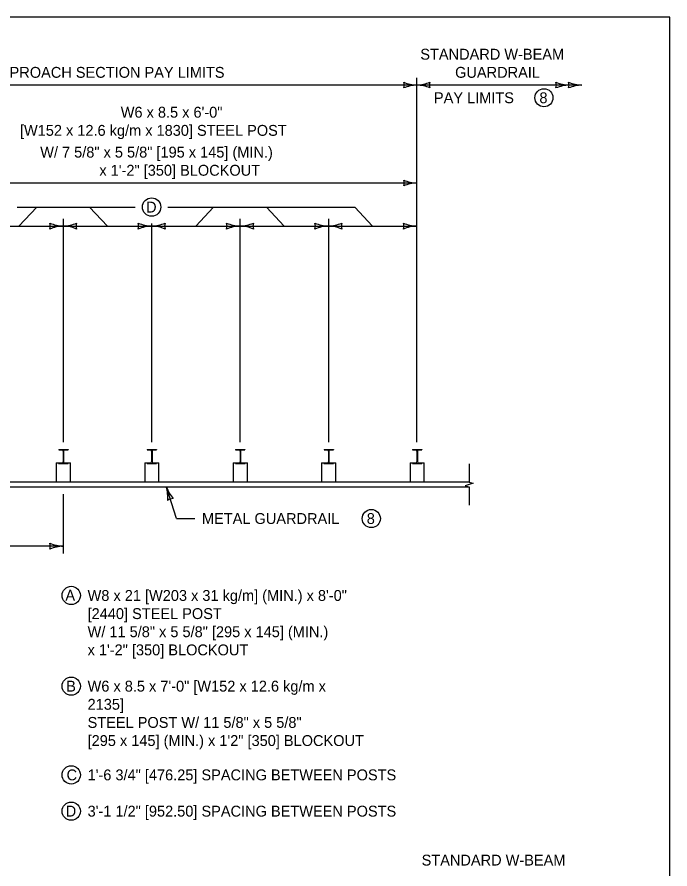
# Model space of a CAD drawing. Extents: x 49991.4 to 50021, y 49987.6 to 50011.4.
# Drawn here: x 50005.013 to 50008.615, y 50006.566 to 50011.263 of the extents above; entities that cross this region are included whole.
import ezdxf

# ---------------------------------------------------------------- set-up
doc = ezdxf.new("R2010")
doc.units = 0
for name, color, linetype in [('Level 1', 7, 'Continuous'), ('Level 2', 7, 'Continuous'), ('Level 3', 7, 'Continuous'), ('Level 6', 7, 'Continuous')]:
    doc.layers.add(name, color=color, linetype=linetype)

msp = doc.modelspace()

# ---------------------------------------------------------------- linework, layer by layer
at = {"layer": 'Level 1'}
for p, q in [((50005.2427, 50008.8793), (50005.2939, 50008.8793)), ((50005.2427, 50008.8793), (50005.2427, 50008.8765)), ((50005.2427, 50008.8765), (50005.2602, 50008.8765)), ((50005.2672, 50008.8696), (50005.2672, 50008.811)), ((50005.2694, 50008.8696), (50005.2694, 50008.811)), ((50005.2764, 50008.8765), (50005.2939, 50008.8765)), ((50005.2939, 50008.8793), (50005.2939, 50008.8765)), ((50005.7306, 50008.8793), (50005.7819, 50008.8793)), ((50005.7306, 50008.8793), (50005.7306, 50008.8765)), ((50005.7306, 50008.8765), (50005.7482, 50008.8765)), ((50005.7551, 50008.8696), (50005.7551, 50008.811)), ((50005.7573, 50008.8696), (50005.7573, 50008.811)), ((50005.7643, 50008.8765), (50005.7819, 50008.8765)), ((50005.7819, 50008.8793), (50005.7819, 50008.8765)), ((50006.2185, 50008.8793), (50006.2698, 50008.8793)), ((50006.2185, 50008.8793), (50006.2185, 50008.8765)), ((50006.2185, 50008.8765), (50006.2361, 50008.8765)), ((50006.2431, 50008.8696), (50006.2431, 50008.811)), ((50006.2453, 50008.8696), (50006.2453, 50008.811)), ((50006.2522, 50008.8765), (50006.2698, 50008.8765)), ((50006.2698, 50008.8793), (50006.2698, 50008.8765)), ((50006.7065, 50008.8793), (50006.7578, 50008.8793)), ((50006.7065, 50008.8793), (50006.7065, 50008.8765)), ((50006.7065, 50008.8765), (50006.7241, 50008.8765)), ((50006.731, 50008.8696), (50006.731, 50008.811)), ((50006.7332, 50008.8696), (50006.7332, 50008.811)), ((50006.7402, 50008.8765), (50006.7578, 50008.8765)), ((50006.7578, 50008.8793), (50006.7578, 50008.8765)), ((50007.1944, 50008.8793), (50007.2457, 50008.8793)), ((50007.1944, 50008.8793), (50007.1944, 50008.8765)), ((50007.1944, 50008.8765), (50007.212, 50008.8765)), ((50007.219, 50008.8696), (50007.219, 50008.811)), ((50007.2212, 50008.8696), (50007.2212, 50008.811)), ((50007.2281, 50008.8765), (50007.2457, 50008.8765)), ((50007.2457, 50008.8793), (50007.2457, 50008.8765)), ((50005.2293, 50008.8041), (50005.2293, 50008.7)), ((50005.2293, 50008.8041), (50005.242, 50008.8041)), ((50005.242, 50008.8013), (50005.242, 50008.8041)), ((50005.242, 50008.8013), (50005.2946, 50008.8013)), ((50005.2427, 50008.8013), (50005.2427, 50008.8041)), ((50005.2427, 50008.8041), (50005.2602, 50008.8041)), ((50005.2764, 50008.8041), (50005.2939, 50008.8041)), ((50005.2939, 50008.8013), (50005.2939, 50008.8041)), ((50005.2946, 50008.8013), (50005.2946, 50008.8041)), ((50005.2946, 50008.8041), (50005.3073, 50008.8041)), ((50005.3073, 50008.7), (50005.3073, 50008.8041)), ((50005.7172, 50008.8044), (50005.7172, 50008.7)), ((50005.7172, 50008.8041), (50005.73, 50008.8041)), ((50005.73, 50008.8013), (50005.73, 50008.8041)), ((50005.73, 50008.8013), (50005.7825, 50008.8013)), ((50005.7306, 50008.8013), (50005.7306, 50008.8041)), ((50005.7306, 50008.8041), (50005.7482, 50008.8041)), ((50005.7643, 50008.8041), (50005.7819, 50008.8041)), ((50005.7819, 50008.8013), (50005.7819, 50008.8041)), ((50005.7825, 50008.8013), (50005.7825, 50008.8041)), ((50005.7825, 50008.8041), (50005.7953, 50008.8041)), ((50005.7953, 50008.7), (50005.7953, 50008.8041)), ((50006.2051, 50008.8041), (50006.2051, 50008.7)), ((50006.2051, 50008.8041), (50006.2179, 50008.8041)), ((50006.2179, 50008.8013), (50006.2179, 50008.8041)), ((50006.2179, 50008.8013), (50006.2705, 50008.8013)), ((50006.2185, 50008.8013), (50006.2185, 50008.8041)), ((50006.2185, 50008.8041), (50006.2361, 50008.8041)), ((50006.2522, 50008.8041), (50006.2698, 50008.8041)), ((50006.2698, 50008.8013), (50006.2698, 50008.8041)), ((50006.2705, 50008.8013), (50006.2705, 50008.8041)), ((50006.2705, 50008.8041), (50006.2832, 50008.8041)), ((50006.2832, 50008.7), (50006.2832, 50008.8041)), ((50006.6931, 50008.8041), (50006.6931, 50008.7)), ((50006.6931, 50008.8041), (50006.7058, 50008.8041)), ((50006.7058, 50008.8013), (50006.7058, 50008.8041)), ((50006.7058, 50008.8013), (50006.7584, 50008.8013)), ((50006.7065, 50008.8013), (50006.7065, 50008.8041)), ((50006.7065, 50008.8041), (50006.7241, 50008.8041)), ((50006.7402, 50008.8041), (50006.7578, 50008.8041)), ((50006.7578, 50008.8013), (50006.7578, 50008.8041)), ((50006.7584, 50008.8013), (50006.7584, 50008.8041)), ((50006.7584, 50008.8041), (50006.7712, 50008.8041)), ((50006.7712, 50008.7), (50006.7712, 50008.8041)), ((50007.181, 50008.8041), (50007.181, 50008.7)), ((50007.181, 50008.8041), (50007.1938, 50008.8041)), ((50007.1938, 50008.8013), (50007.1938, 50008.8041)), ((50007.1938, 50008.8013), (50007.2464, 50008.8013)), ((50007.1944, 50008.8013), (50007.1944, 50008.8041)), ((50007.1944, 50008.8041), (50007.212, 50008.8041)), ((50007.2281, 50008.8041), (50007.2457, 50008.8041)), ((50007.2457, 50008.8013), (50007.2457, 50008.8041)), ((50007.2464, 50008.8013), (50007.2464, 50008.8041)), ((50007.2464, 50008.8041), (50007.2591, 50008.8041)), ((50007.2591, 50008.7), (50007.2591, 50008.8041)), ((50007.5069, 50008.6714), (50003.1301, 50008.6714)), ((50003.2303, 50008.7), (50007.5069, 50008.7))]:
    msp.add_line(p, q, dxfattribs=at)
msp.add_lwpolyline([(50008.6146, 50011.2628), (50000.3356, 50011.2628), (50000.3356, 50000.0624), (50008.6146, 50000.0624)], close=True, dxfattribs=at)
for centre, start, end in [((50005.2602, 50008.8696), 0, 90), ((50005.2764, 50008.8696), 90, 180), ((50005.7482, 50008.8696), 0, 90), ((50005.7643, 50008.8696), 90, 180), ((50006.2361, 50008.8696), 0, 90), ((50006.2522, 50008.8696), 90, 180), ((50006.7241, 50008.8696), 0, 90), ((50006.7402, 50008.8696), 90, 180), ((50007.212, 50008.8696), 0, 90), ((50007.2281, 50008.8696), 90, 180), ((50005.2602, 50008.811), 270, 0), ((50005.2764, 50008.811), 180, 270), ((50005.7482, 50008.811), 270, 0), ((50005.7643, 50008.811), 180, 270), ((50006.2361, 50008.811), 270, 0), ((50006.2522, 50008.811), 180, 270), ((50006.7241, 50008.811), 270, 0), ((50006.7402, 50008.811), 180, 270), ((50007.212, 50008.811), 270, 0), ((50007.2281, 50008.811), 180, 270)]:
    msp.add_arc(centre, 0.00696, start, end, dxfattribs=at)
at = {"layer": 'Level 2'}
for centre, radius in [((50007.9193, 50010.8177), 0.05), ((50005.7549, 50010.215), 0.0505), ((50006.9668, 50008.4978), 0.05), ((50005.3115, 50008.0736), 0.0504), ((50005.3115, 50007.5736), 0.0504), ((50005.3115, 50007.0844), 0.0504), ((50005.3115, 50006.8844), 0.0505)]:
    msp.add_circle(centre, radius, dxfattribs=at)
at = {"layer": 'Level 3'}
for p, q in [((50007.2181, 50008.9193), (50007.2181, 50010.9278)), ((50007.2181, 50010.8878), (50003.3165, 50010.8878)), ((50008.1278, 50010.8878), (50007.2181, 50010.8878)), ((50004.7796, 50010.3479), (50007.2181, 50010.3479)), ((50005.0126, 50010.215), (50005.6645, 50010.215)), ((50005.1215, 50010.215), (50005.0234, 50010.1105)), ((50005.4129, 50010.215), (50005.5111, 50010.1105)), ((50005.8454, 50010.215), (50006.8761, 50010.215)), ((50006.0969, 50010.215), (50005.9988, 50010.1105)), ((50006.3883, 50010.215), (50006.4865, 50010.1105)), ((50006.8761, 50010.215), (50006.9742, 50010.1105)), ((50005.2672, 50010.1505), (50005.2672, 50008.9193)), ((50005.7549, 50010.1245), (50005.7549, 50008.9193)), ((50006.2426, 50010.1505), (50006.2426, 50008.9193)), ((50006.7303, 50010.1505), (50006.7303, 50008.9193)), ((50004.7796, 50010.1105), (50005.2672, 50010.1105)), ((50005.2672, 50010.1105), (50005.7549, 50010.1105)), ((50005.7549, 50010.1105), (50006.2426, 50010.1105)), ((50006.2426, 50010.1105), (50006.7303, 50010.1105)), ((50006.7303, 50010.1105), (50007.2181, 50010.1105)), ((50005.893, 50008.4978), (50005.8364, 50008.6714)), ((50005.2673, 50008.6315), (50005.2673, 50008.3052)), ((50005.893, 50008.4978), (50005.9928, 50008.4978)), ((50005.2673, 50008.3452), (50003.3165, 50008.3452))]:
    msp.add_line(p, q, dxfattribs=at)
for centre, radius, start, end in [((50007.2268, 50011.0988), 0.2113, 247.456, 267.6395), ((50007.0963, 50010.8878), 0.0521, 342.1388, 17.8612), ((50007.229, 50010.6666), 0.2214, 92.8273, 112.0772), ((50007.2072, 50011.1089), 0.2214, 272.8273, 292.0772), ((50007.2094, 50010.6767), 0.2113, 67.456, 87.6395), ((50007.3399, 50010.8878), 0.0521, 162.1388, 197.8612), ((50008.0667, 50011.0988), 0.2113, 247.456, 267.6395), ((50007.9362, 50010.8878), 0.0521, 342.1388, 17.8612), ((50008.0689, 50010.6666), 0.2214, 92.8273, 112.0772), ((50008.1365, 50011.0988), 0.2113, 247.456, 267.6395), ((50008.006, 50010.8878), 0.0521, 342.1388, 17.8612), ((50008.1387, 50010.6666), 0.2214, 92.8273, 112.0772), ((50007.2268, 50010.559), 0.2113, 247.456, 267.6395), ((50007.0963, 50010.3479), 0.0521, 342.1388, 17.8612), ((50007.229, 50010.1267), 0.2214, 92.8273, 112.0772), ((50005.2762, 50010.3272), 0.2168, 247.456, 267.6395), ((50005.1422, 50010.1105), 0.0534, 342.1388, 17.8612), ((50005.256, 50010.3375), 0.2273, 272.8273, 292.0772), ((50005.3923, 50010.1105), 0.0534, 162.1388, 197.8612), ((50005.7639, 50010.3272), 0.2168, 247.456, 267.6395), ((50005.6299, 50010.1105), 0.0534, 342.1388, 17.8612), ((50005.7437, 50010.3375), 0.2273, 272.8273, 292.0772), ((50005.88, 50010.1105), 0.0534, 162.1388, 197.8612), ((50006.2515, 50010.3272), 0.2168, 247.456, 267.6395), ((50006.1176, 50010.1105), 0.0534, 342.1388, 17.8612), ((50006.2314, 50010.3375), 0.2273, 272.8273, 292.0772), ((50006.3677, 50010.1105), 0.0534, 162.1388, 197.8612), ((50006.7392, 50010.3272), 0.2168, 247.456, 267.6395), ((50006.6052, 50010.1105), 0.0534, 342.1388, 17.8612), ((50006.7191, 50010.3375), 0.2273, 272.8273, 292.0772), ((50006.8554, 50010.1105), 0.0534, 162.1388, 197.8612), ((50007.227, 50010.3272), 0.2168, 247.456, 267.6395), ((50007.093, 50010.1105), 0.0534, 342.1388, 17.8612), ((50005.2784, 50009.8835), 0.2273, 92.8273, 112.0772), ((50005.2583, 50009.8939), 0.2168, 67.456, 87.6395), ((50005.7661, 50009.8835), 0.2273, 92.8273, 112.0772), ((50005.746, 50009.8939), 0.2168, 67.456, 87.6395), ((50006.2538, 50009.8835), 0.2273, 92.8273, 112.0772), ((50006.2337, 50009.8939), 0.2168, 67.456, 87.6395), ((50006.7415, 50009.8835), 0.2273, 92.8273, 112.0772), ((50006.7214, 50009.8939), 0.2168, 67.456, 87.6395), ((50007.2293, 50009.8835), 0.2273, 92.8273, 112.0772), ((50005.633, 50008.6144), 0.2113, 355.4765, 15.66), ((50006.0434, 50008.7502), 0.2214, 200.8478, 220.0976), ((50005.8741, 50008.5556), 0.0521, 90.1593, 125.8816), ((50005.2762, 50008.5619), 0.2168, 247.456, 267.6395), ((50005.1422, 50008.3452), 0.0534, 342.1388, 17.8612), ((50005.2785, 50008.1183), 0.2273, 92.8273, 112.0772)]:
    msp.add_arc(centre, radius, start, end, dxfattribs=at)
at = {"layer": 'Level 6'}
for p, q in [((50007.5069, 50008.8), (50007.5069, 50008.6982)), ((50007.5285, 50008.6936), (50007.4852, 50008.6782)), ((50007.4852, 50008.6782), (50007.5069, 50008.6728)), ((50007.5069, 50008.6982), (50007.5285, 50008.6936)), ((50007.5069, 50008.6728), (50007.5069, 50008.5714))]:
    msp.add_line(p, q, dxfattribs=at)

# ---------------------------------------------------------------- texts
at = {"layer": 'Level 2'}
for s, p in [('STANDARD W-BEAM', (50007.2373, 50011.0278)), ('25\'-0" [7.62 m] BRIDGE APPROACH SECTION PAY LIMITS', (50003.9957, 50010.9278)), ('GUARDRAIL', (50007.4292, 50010.9278)), ('PAY LIMITS', (50007.3125, 50010.7878)), ('8', (50007.8944, 50010.7877)), ('W6 x 8.5 x 6\'-0"', (50005.5847, 50010.7079)), (' [W152 x 12.6 kg/m x 1830] STEEL POST', (50005.0064, 50010.6079)), ('W/ 7 5/8" x 5 5/8" [195 x 145] (MIN.)', (50005.1405, 50010.4879)), (' x 1\'-2" [350] BLOCKOUT', (50005.4446, 50010.3879)), ('D', (50005.7246, 50010.185)), ('METAL GUARDRAIL', (50006.0328, 50008.4678)), ('8', (50006.9419, 50008.4677)), ('A', (50005.2794, 50008.0449)), ('W8 x 21 [W203 x 31 kg/m] (MIN.) x 8\'-0" ', (50005.4019, 50008.0436)), ('[2440] STEEL POST', (50005.4019, 50007.9436)), ('W/ 11 5/8" x 5 5/8" [295 x 145] (MIN.) ', (50005.4019, 50007.8436)), ('x 1\'-2" [350] BLOCKOUT', (50005.4019, 50007.7436)), ('B', (50005.2838, 50007.5436)), ('W6 x 8.5 x 7\'-0" [W152 x 12.6 kg/m x ', (50005.4019, 50007.5436)), ('2135] ', (50005.4019, 50007.4436)), ('STEEL POST W/ 11 5/8" x 5 5/8" ', (50005.4019, 50007.3436)), ('[295 x 145] (MIN.) x 1\'2" [350] BLOCKOUT', (50005.4019, 50007.2436)), ('1\'-6 3/4" [476.25] SPACING BETWEEN POSTS', (50005.4019, 50007.0544)), ('C', (50005.286, 50007.0543)), ('D', (50005.2811, 50006.8544)), ('3\'-1 1/2" [952.50] SPACING BETWEEN POSTS', (50005.4019, 50006.8544)), ('STANDARD W-BEAM', (50007.2446, 50006.5845))]:
    msp.add_text(s, height=0.06, dxfattribs=at).set_placement(p)

doc.saveas('drawing.dxf')
